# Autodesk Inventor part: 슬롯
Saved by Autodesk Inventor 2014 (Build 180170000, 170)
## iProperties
Created: 2025-09
Part Number: 슬롯
Material: 일반
Document SubType Name: Modeling
Designer: dg
Density: 1 g/cm^3
Appearance: 기본값
Author: dg
Author: jhkim
Creation Date: 2025-09-02
Sending System: Autodesk Inventor 2026
Preprocessor: ST-DEVELOPER v20.1
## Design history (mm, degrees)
node "슬롯1"
node "솔리드1"
node "기준1"
